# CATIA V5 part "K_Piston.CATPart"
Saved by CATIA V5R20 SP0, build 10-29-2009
Part number: Piston
Property "Diamètre joint": 20 mm
Property "Longueur corps du piston": 300 mm
Property "Diamètre piston": 100 mm
Property "Epaiseur piston": 5 mm
Property "Longueur piston": 640 mm
Bounding box of the stored display mesh (mm): x -44.97 to 44.97, y -45 to 45, z 0 to 660
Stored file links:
  C:\Users\thinkmotion1\Desktop\Khaled_IAO_Pack2\Problemes\IAO_2010_1405_jpalas\IAO_PALAS\Khaled_Palas\K_Piston.CATPart
  C:\Users\thinkmotion1\Desktop\Khaled_IAO_Pack2\Problemes\IAO_2010_1405_jpalas\IAO_PALAS\Khaled_Palas\K_Palas.CATProduct
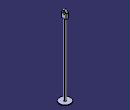
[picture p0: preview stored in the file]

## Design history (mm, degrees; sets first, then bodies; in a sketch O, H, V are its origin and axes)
External parameters (linked from other documents)
  `External.Niv 1 Longueur piston` = 640 mm
Body1 (main body)
  Sketch1 on zx-plane, origin (0, 0, 0), H (0, 0, 1), V (1, 0, 0)
    line L1 (660, 0) -> (0, 0)
    line L2 (0, 0) -> (0, 45)
    line L3 (0, 45) -> (5, 45)
    line L4 (5, 45) -> (5, 10)
    line L5 (5, 10) -> (600, 10)
    line L6 (600, 10) -> (600, 20)
    line L7 (600, 20) -> (640, 20)
    arc A1 centre (640, 0) radius 20 from (660, 0) to (640, 20) ccw
    point P8 (640, 0)
    length L3 = 5
    length L2 = 45
    length L7 = 40
    radius A1 = 20
    distance L5 L1 = 10
    distance P8 L2 = 640
    horizontal: L1 H, L3 H, L5 H, L7 H
    vertical: L2 V, L4 V, L6 V
    coincidence: P8 L1
    tangency: A1 L7
  Shaft1: profile Sketch1, axis Sketch1.L1, angle 360
  Sketch2 on face of Shaft1 from Sketch1.L6, origin (10, 0, 600), H (1, 0, 0), V (0, 1, 0)
    line L1 (-30, 25) -> (-20, 25)
    line L2 (-20, 25) -> (-20, -25)
    line L3 (-20, -25) -> (-30, -25)
    line L4 (-30, -25) -> (-30, 25)
    reference projected circle E1 centre (-10, 0) radius 10 from edge [face of Shaft1 from Sketch1.L5 | face of Shaft1 from Sketch1.L6]
    reference projected circle E2 centre (-10, 0) radius 20 from edge [face of Shaft1 from Sketch1.L6 | face of Shaft1 from Sketch1.L7]
    line L5 (10, 20) -> (0, 20)
    line L6 (0, 20) -> (0, -20)
    line L7 (0, -20) -> (10, -20)
    line L8 (10, -20) -> (10, 20)
    reference projected circle E3 centre (-10, 0) radius 20 from edge [face of Shaft1 from Sketch1.L6 | face of Shaft1 from Sketch1.L7]
    reference projected circle E4 centre (-10, 0) radius 10 from edge [face of Shaft1 from Sketch1.L5 | face of Shaft1 from Sketch1.L6]
    reference projected circle E5 centre (-10, 0) radius 20 from edge [face of Shaft1 from Sketch1.L6 | face of Shaft1 from Sketch1.L7]
    reference projected circle E6 centre (-10, 0) radius 20 from edge [face of Shaft1 from Sketch1.L6 | face of Shaft1 from Sketch1.L7]
    reference projected circle E7 centre (-10, 0) radius 20 from edge [face of Shaft1 from Sketch1.L6 | face of Shaft1 from Sketch1.L7]
    length L4 = 50
    distance L3 E3 = 5
    horizontal: L1 H, L3 H, L5 H, L7 H
    vertical: L2 V, L4 V, L6 V, L8 V
    tangency: L2 E1, L4 E2, L6 E4, L8 E5, L7 E6, L5 E7
  Pocket1: profile Sketch2, direction (0, 0, 1), length 60
  Sketch3 on face of Pocket1 from Sketch2.L2, origin (-10, 0.6923, 420.7994), H (0, 1, 0), V (0, 0, -1)
    point P1 (-0.6923, -219.2006)
    reference projected arc E1 centre (-0.6923, -219.2006) radius 17.3205 from (-18.0128, -219.2006) to (16.6282, -219.2006) ccw from edge [face of Shaft1 from Sketch1.A1 | face of Pocket1 from Sketch2.L2]
    concentricity: E1 P1
  Hole1: placed by Sketch3, at (-10, 0, 640) direction (1, 0, 0), diameter 20, through (limit type 3)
